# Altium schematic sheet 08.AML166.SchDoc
size A3; CheckedBy: <审核人员>; Author: 刘时杰; DocumentNumber: 7; SheetNumber: 7; SheetTotal: 8; PageSetup: Record=PageOptions|CenterHorizontal=True|CenterVertical=True|PrintScale=1.00|XCorrection=1.00|YCorrection=1.00|PrintKind=0|BorderSize=5000000|LeftOffset=0|BottomOffset=0|Orientation=2|PaperLength=1000|PaperWidth=1000|Scale=100|PaperSource=7|PrintQuality=600|MediaType=1|DitherType=10|PaperKind=A4|PrintScaleMode=1; CheckDate: <审核日期>; SheetName: AML166_ADC24; SheetVersion: Rev.D; SheetDescription: AML166评估24位ADC性能电路; ProductName: AML166; ProductModel: AML166-Core
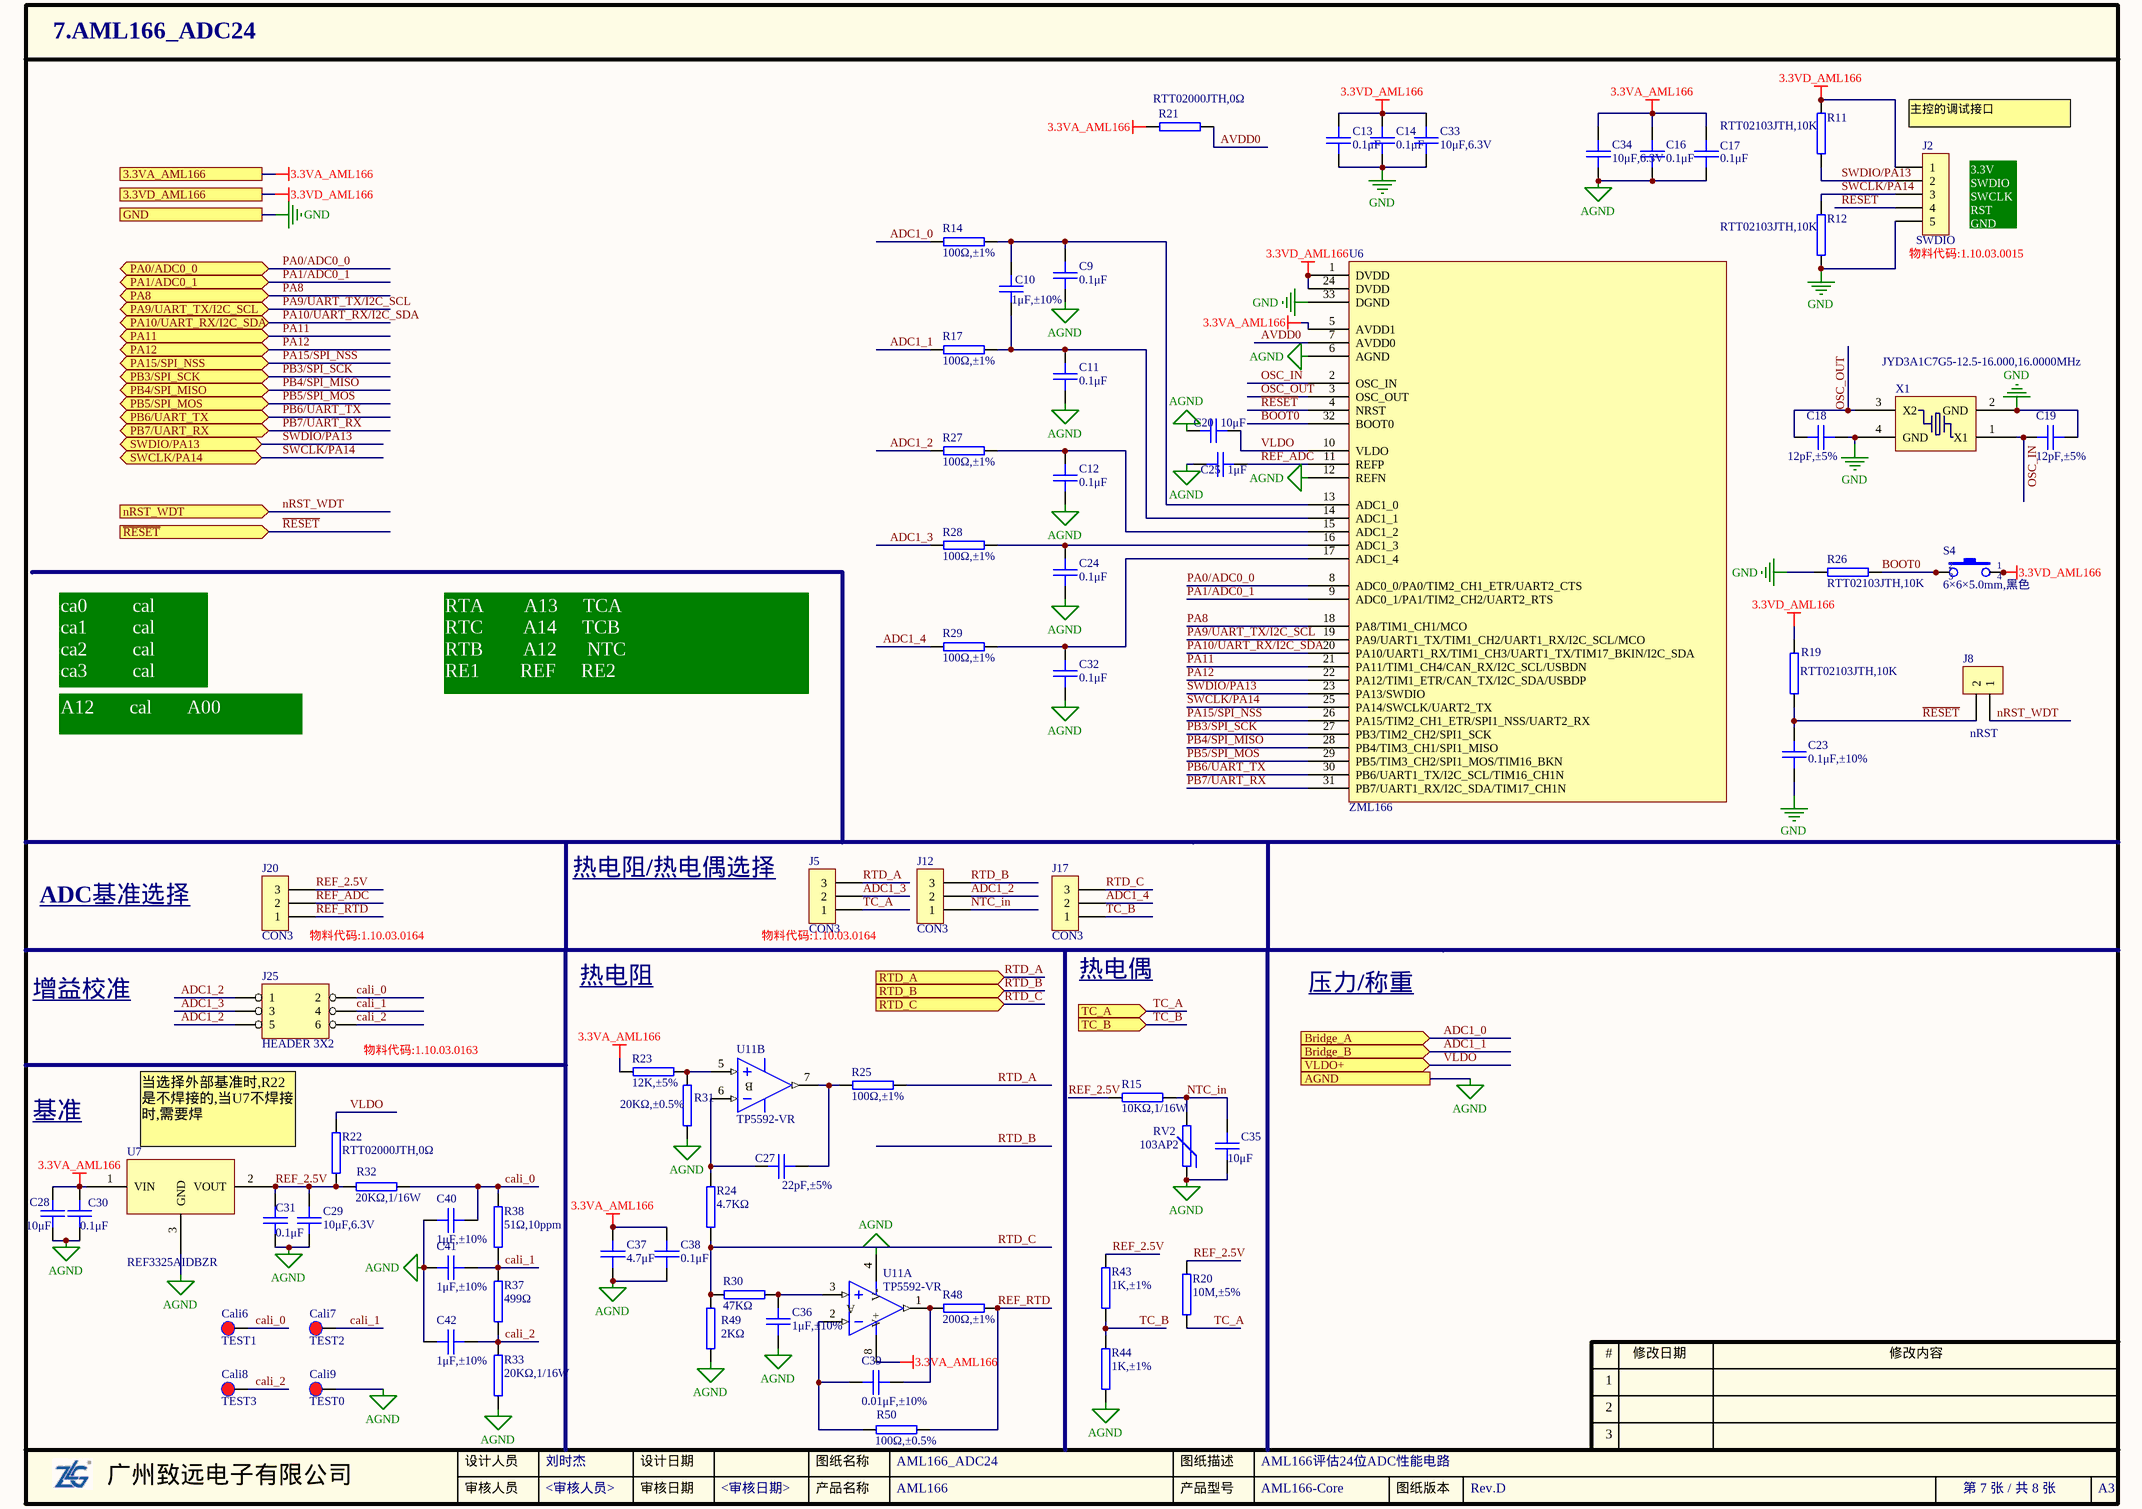
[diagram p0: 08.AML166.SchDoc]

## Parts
C9  0.1μF  [0402C]
C10  1μF,±10%  [0402C]
C11  0.1μF  [0402C]
C12  0.1μF  [0402C]
C13  0.1μF  [0402C]
C14  0.1μF  [0402C]
C16  0.1μF  [0402C]
C17  0.1μF  [0402C]
C18  12pF,±5%  [0402C]
C19  12pF,±5%  [0402C]
C20  10μF  [0603C]
C23  0.1μF,±10%  [0402C]
C24  0.1μF  [0402C]
C25  1μF  [0402C]
C27  22pF,±5%  [0402C]
C28  10μF  [0603C]
C29  10μF,6.3V  [0603C]
C30  0.1μF  [0402C]
C31  0.1μF  [0402C]
C32  0.1μF  [0402C]
C33  10μF,6.3V  [0603C]
C34  10μF,6.3V  [0603C]
C35  10μF  [0603C]
C36  1μF,±10%  [0402C]
C37  4.7μF  [0402C]
C38  0.1μF  [0402C]
C39  0.01μF,±10%  [0402C]
C40  1μF,±10%  [0402C]
C41  1μF,±10%  [0402C]
C42  1μF,±10%  [0402C]
Cali6  TEST1  [PAD-25/40]  (no BOM)
Cali7  TEST2  [PAD-25/40]  (no BOM)
Cali8  TEST3  [PAD-25/40]  (no BOM)
Cali9  TEST0  [PAD-25/40]  (no BOM)
J2  SWDIO  [SIP-5-2.54-6.0-R90]
J5  CON3  [SIP-3-2.54]
J8  nRST  [SIP-2-2.54]
J12  CON3  [SIP-3-2.54]
J17  CON3  [SIP-3-2.54]
J20  CON3  [SIP-3-2.54]
J25  HEADER 3X2  [IDC-6-2.54]
R11  RTT02103JTH,10K  [0402R]
R12  RTT02103JTH,10K  [0402R]
R14  100Ω,±1%  [0402R]
R15  10KΩ,1/16W  [0603R]
R17  100Ω,±1%  [0402R]
R19  RTT02103JTH,10K  [0402R]
R20  10M,±5%  [0402R]
R21  RTT02000JTH,0Ω  [0402R]
R22  RTT02000JTH,0Ω  [0402R]  (no BOM)
R23  12K,±5%  [0402R]
R24  4.7KΩ  [0603R]
R25  100Ω,±1%  [0402R]
R26  RTT02103JTH,10K  [0402R]
R27  100Ω,±1%  [0402R]
R28  100Ω,±1%  [0402R]
R29  100Ω,±1%  [0402R]
R30  47KΩ  [0603R]
R31  20KΩ,±0.5%  [0402R]
R32  20KΩ,1/16W  [0603R]
R33  20KΩ,1/16W  [0603R]
R37  499Ω  [0603R]
R38  51Ω,10ppm  [0603R]
R43  1K,±1%  [0402R]
R44  1K,±1%  [0402R]
R48  200Ω,±1%  [0402R]
R49  2KΩ  [0603R]
R50  100Ω,±0.5%  [0402R]
RV2  103AP2  [RESRR254W35L380T260H850P]
S4  value 6×6×5.0mm,黑色  [KEY-6S]  (hidden comment: SW-PB4P)
U6  ZML166  [QFN50P500X500X85-33N]
U7  REF3325AIDBZR  [SOT-23]
U11  TP5592-VR  [SOP65P490X120-8N]  (parts A,B of 2)
X1  JYD3A1C7G5-12.5-16.000,16.0000MHz  [OSCCC250X320X80-4N]

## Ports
3.3VA_AML166, 3.3VD_AML166, AGND, Bridge_A (in), Bridge_B (in), GND, nRST_WDT (in), PA0/ADC0_0 (bidir), PA1/ADC0_1 (bidir), PA8 (bidir), PA9/UART_TX/I2C_SCL (bidir), PA10/UART_RX/I2C_SDA (bidir), PA11 (bidir), PA12 (bidir), PA15/SPI_NSS (bidir), PB3/SPI_SCK (bidir), PB4/SPI_MISO (bidir), PB5/SPI_MOS (bidir), PB6/UART_TX (bidir), PB7/UART_RX (bidir), RTD_A (in), RTD_B (in), RTD_C (in), SWCLK/PA14 (bidir), SWDIO/PA13 (bidir), TC_A (in), TC_B (in), VLDO+ (in), ~{RESET} (in)

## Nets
3.3VA_AML166: C16.1 C17.1 C28.2 C30.1 C34.2 C37.1 C38.1 R21.1 R23.1 U6.5(AVDD1) U7.1(VIN) U11.8(V+) ; port 3.3VA_AML166
3.3VD_AML166: C13.1 C14.1 C33.2 J2.1 R11.2 R19.1 S4.1 S4.4 U6.1(DVDD) U6.24(DVDD) ; port 3.3VD_AML166
AGND: C9.2 C11.2 C12.2 C16.2 C17.2 C20.2 C24.2 C25.1 C28.1 C29.1 C30.2 C31.2 C32.2 C34.1 C35.1 C36.2 C37.2 C38.2 C40.1 C41.1 C42.1 Cali9.1 R31.1 R33.2 R44.2 R49.1 RV2.1 U6.6(AGND) U6.12(REFN) U7.3(GND) U11.4(V-) ; port AGND
GND: C13.2 C14.2 C18.1 C19.2 C23.2 C33.1 J2.5 R12.1 R26.2 U6.33(DGND) X1.2(GND) X1.4(GND) ; port GND
ADC1_0: R14.1 ; port Bridge_A
ADC1_1: R17.1 ; port Bridge_B
ADC1_2: J12.2 J25.1 J25.5 R27.1
ADC1_3: J5.2 J25.3 R28.1
ADC1_4: J17.2 R29.1
AVDD0: R21.2 U6.7(AVDD0)
BOOT0: R26.1 S4.2 S4.3 U6.32(BOOT0)
cali_0: C40.2 Cali6.1 J25.2 R32.1 R38.1
cali_1: C41.2 Cali7.1 J25.4 R37.2 R38.2
cali_2: C42.2 Cali8.1 J25.6 R33.1 R37.1
nRST_WDT: J8.1 ; port nRST_WDT
NTC_in: C35.2 J12.1 R15.2 RV2.2
OSC_IN: C19.1 U6.2(OSC_IN) X1.1(X1)
OSC_OUT: C18.2 U6.3(OSC_OUT) X1.3(X2)
PA0/ADC0_0: U6.8(ADC0_0/PA0/TIM2_CH1_ETR/UART2_CTS) ; port PA0/ADC0_0
PA1/ADC0_1: U6.9(ADC0_1/PA1/TIM2_CH2/UART2_RTS) ; port PA1/ADC0_1
PA8: U6.18(PA8/TIM1_CH1/MCO) ; port PA8
PA9/UART_TX/I2C_SCL: U6.19(PA9/UART1_TX/TIM1_CH2/UART1_RX/I2C_SCL/MCO) ; port PA9/UART_TX/I2C_SCL
PA10/UART_RX/I2C_SDA: U6.20(PA10/UART1_RX/TIM1_CH3/UART1_TX/TIM17_BKIN/I2C_SDA) ; port PA10/UART_RX/I2C_SDA
PA11: U6.21(PA11/TIM1_CH4/CAN_RX/I2C_SCL/USBDN) ; port PA11
PA12: U6.22(PA12/TIM1_ETR/CAN_TX/I2C_SDA/USBDP) ; port PA12
PA15/SPI_NSS: U6.26(PA15/TIM2_CH1_ETR/SPI1_NSS/UART2_RX) ; port PA15/SPI_NSS
PB3/SPI_SCK: U6.27(PB3/TIM2_CH2/SPI1_SCK) ; port PB3/SPI_SCK
PB4/SPI_MISO: U6.28(PB4/TIM3_CH1/SPI1_MISO) ; port PB4/SPI_MISO
PB5/SPI_MOS: U6.29(PB5/TIM3_CH2/SPI1_MOS/TIM16_BKN) ; port PB5/SPI_MOS
PB6/UART_TX: U6.30(PB6/UART1_TX/I2C_SCL/TIM16_CH1N) ; port PB6/UART_TX
PB7/UART_RX: U6.31(PB7/UART1_RX/I2C_SDA/TIM17_CH1N) ; port PB7/UART_RX
~{RESET}: C23.1 J2.4 J8.2 R19.2 U6.4(NRST) ; port ~{RESET}
REF_2.5V: C29.2 C31.1 J20.3 R15.1 R20.2 R22.1 R32.2 R43.2 U7.2(VOUT)
REF_ADC: C25.2 J20.2 U6.11(REFP)
REF_RTD: J20.1 R48.2 R50.1
RTD_A: J5.3 R25.2 ; port RTD_A
RTD_B: J12.3 ; port RTD_B
RTD_C: J17.3 R24.1 R30.1 R49.2 ; port RTD_C
SWCLK/PA14: J2.3 R12.2 U6.25(PA14/SWCLK/UART2_TX) ; port SWCLK/PA14
SWDIO/PA13: J2.2 R11.1 U6.23(PA13/SWDIO) ; port SWDIO/PA13
TC_A: J5.1 R20.1 ; port TC_A
TC_B: J17.1 R43.1 R44.1 ; port TC_B
VLDO: C20.1 R22.2 U6.10(VLDO) ; port VLDO+
NetC9_1: C9.1 C10.1 R14.2 U6.13(ADC1_0)
NetC10_2: C10.2 C11.1 R17.2 U6.14(ADC1_1)
NetC12_1: C12.1 R27.2 U6.15(ADC1_2)
NetC24_1: C24.1 R28.2 U6.16(ADC1_3)
NetC27_1: C27.1 R24.2 U11.6(IN-)
NetC27_2: C27.2 R25.1 U11.7(OUT)
NetC32_1: C32.1 R29.2 U6.17(ADC1_4)
NetC36_1: C36.1 R30.2 U11.3(IN+)
NetC39_1: C39.1 R50.2 U11.2(IN-)
NetC39_2: C39.2 R48.1 U11.1(OUT)
NetR23_2: R23.2 R31.2 U11.5(IN+)

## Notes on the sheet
- (near J2) 主控的调试接口
- (near J2) 3.3V
  SWDIO
  SWCLK
  RST
  GND
- (near J2) 物料代码:1.10.03.0015
- ca0         cal
  ca1         cal
  ca2         cal
  ca3         cal
- RTA        A13     TCA
  RTC        A14     TCB
  RTB        A12      NTC
  RE1        REF     RE2
- A12       cal       A00
- ADC基准选择
- 热电阻/热电偶选择
- (near J20) 物料代码:1.10.03.0164
- 热电阻
- (near J5) 物料代码:1.10.03.0164
- (near J17) 热电偶
- 压力/称重
- 增益校准
- (near J25) 物料代码:1.10.03.0163
- 基准
- 当选择外部基准时,R22是不焊接的,当U7不焊接时,需要焊

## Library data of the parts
C9 C11-C14 C16 C17 C24 C30-C32 C38 = 1.02.17.0118: GCM155R71E104KE02D,0.1μF,±10%,25V,X7R,0402,muRata,RoHS; 名称: 电容; 封装: 0402; 贴片和直插: SMT; PCB备注: 161012yjh; 器件优选方案: 正常状态，可以选用
C10 C25 C36 C40-C42 = 1.02.17.0092: GRM155R61C105KA12D,1μF,±10% ,16V,X5R,0402,muRata,RoHS; 名称: 电容; 封装: 0402; 贴片和直插: SMT; PCB备注: 无数据手册，依据采购部提供的信息添加的封装。; 器件优选方案: 正常状态，可以选用
C18 C19 = 1.02.17.0018: GRM1555C1H120JA01D,12pF,±5%,50V,C0G,0402,muRata,RoHS; 名称: 电容; 封装: 0402; 设备封装名称: C0402_12PF_COG_50V_5%; 贴片和直插: SMT; 器件优选方案: 正常状态，可以选用
C20 C28 C29 C33-C35 = 1.02.01.0065: 10μF,6.3V,X5R,GRM188R60J106M****,0603,Murata,RoHS; 名称: 电容; 封装: 0603; 贴片和直插: SMT; 器件优选方案: 正常状态，可以选用
C23 = 1.02.17.0006: GRM155R71C104KA88D,0.1μF,±10%,16V,X7R,0402,muRata,RoHS; 名称: 电容; 封装: 0402; 设备封装名称: C0402_0.1uF_X7R_16V_10%; 贴片和直插: SMT; 器件优选方案: 正常状态，可以选用
C27 = 1.02.17.0036: GRM1555C1H220JA01D,22pF,±5%,50V,C0G,0402,muRata,RoHS; 名称: 电容; 封装: 0402; 设备封装名称: C0402_22PF_NPO_50V_5%; 贴片和直插: SMT; 器件优选方案: 正常状态，可以选用
C37 = 1.02.17.0073: GRM155R60J475ME87D,4.7μF,±20%,6.3V,X5R,0402,muRata,RoHS; 名称: 电容; 封装: 0402; 贴片和直插: SMT; 器件优选方案: 正常状态，可以选用
C39 = 1.02.17.0019: GRM155R71H103KA88D,0.01μF,±10%,50V,X7R,0402,muRata,RoHS; 名称: 电容; 封装: 0402; 设备封装名称: C0402_0.01uF_X7R_50V_10%; 贴片和直插: SMT; 器件优选方案: 正常状态，可以选用
Cali6-Cali9 = TEST-DOT
J2 = CON5: Connector; 物料代码: 1.10.03.0015
J5 J12 J17 J20 = CON3: Connector
J8 = CON2: Connector; 物料代码: 1.10.03.0164
R11 R12 R19 R26 = 1.01.17.0006: RTT02103JTH,10K,±5%,0402,RALEC,RoHS; 名称: 电阻; 封装: 0402; 设备封装名称: R0402_10K; 贴片和直插: SMT; 器件优选方案: 正常状态，可以选用
R14 R17 R25 R27-R29 = 1.01.17.0029: 100Ω,±1%,0402,RALEC,RoHS; 名称: 电阻; 封装: 0402; 设备封装名称: R0402_100R_1%; 贴片和直插: SMT; 器件优选方案: 正常状态，可以选用
R15 = 1.01.01.0192: 10KΩ,1/16W,10PPM/℃,±0.1%,0603,Viking,RoHS; 名称: 电阻; 封装: 0603; 设备封装名称: R0603_10K_0.1%; 贴片和直插: SMT; 器件优选方案: 临时/偏门物料/不主推物料，谨慎选用
R20 = 1.01.17.0005: 10M,±5%,0402,RALEC,RoHS; 名称: 电阻; 封装: 0402; 设备封装名称: R0402_10M; 贴片和直插: SMT; 器件优选方案: 正常状态，可以选用
R21 R22 = 1.01.17.0004: RTT02000JTH,0Ω,±5%,0402,RALEC,RoHS; 名称: 电阻; 封装: 0402; 设备封装名称: R0402_0R; 贴片和直插: SMT; 器件优选方案: 正常状态，可以选用
R23 = 1.01.17.0035: 12K,±5%,0402,RALEC,RoHS; 名称: 电阻; 封装: 0402; 设备封装名称: R0402_12K; 贴片和直插: SMT; 器件优选方案: 正常状态，可以选用
R24 = 1.01.01.0045: 4.7KΩ,0603,*,RoHS; 名称: 电阻; 封装: 0603; 设备封装名称: R0603_4.7K; 厂商: Ralec; 贴片和直插: SMT; 器件优选方案: 正常状态，可以选用
R30 = 1.01.01.0060: 47KΩ,0603,*,RoHS; 名称: 电阻; 封装: 0603; 设备封装名称: R0603_47K; 厂商: Ralec; 贴片和直插: SMT; 器件优选方案: 正常状态，可以选用
R31 = 1.01.17.0053: 20KΩ,±0.5%,0402,RoHS; 名称: 电阻; 封装: 0402; 设备封装名称: R0402_20K_0.5%; 厂商: Ralec; 贴片和直插: SMT; 器件优选方案: 正常状态，可以选用
R32 R33 = 1.01.01.0207: 20KΩ,1/16W,10PPM/℃,±0.1%,0603,Viking,RoHS; 名称: 电阻; 封装: 0603; 贴片和直插: SMT; 器件优选方案: 临时/偏门物料/不主推物料，谨慎选用
R37 = 1.01.01.0155: 499Ω,RN731JTTD,4990B10,0603,KOA,RoHS; 名称: 电阻; 封装: 0603; 设备封装名称: R0603_499R_0.1%; 贴片和直插: SMT; 器件优选方案: 临时/偏门物料/不主推物料，谨慎选用
R38 = 1.01.01.0215: 51Ω,10ppm,±0.1%,AR03BTB0510,0603,Viking,RoHS; 名称: 电阻; 封装: 0603; 贴片和直插: SMT; 器件优选方案: 临时/偏门物料/不主推物料，谨慎选用
R43 R44 = 1.01.17.0016: 1K,±1%,0402,RALEC,RoHS; 名称: 电阻; 封装: 0402; 设备封装名称: R0402_1K_1%; 贴片和直插: SMT; 器件优选方案: 正常状态，可以选用
R48 = 1.01.17.0073: 200Ω,±1%,0402,RoHS; 名称: 电阻; 封装: 0402; 设备封装名称: R0402_200R_1%; 厂商: Ralec; 贴片和直插: SMT; 器件优选方案: 正常状态，可以选用
R49 = 1.01.01.0157: 2KΩ,RN731JTTD,2001B10,0603,KOA,RoHS; 名称: 电阻; 封装: 0603; 设备封装名称: R0603_2K_0.1%; 贴片和直插: SMT; 器件优选方案: 临时/偏门物料/不主推物料，谨慎选用
R50 = 1.01.17.0052: 100Ω,±0.5%,0402,RoHS; 名称: 电阻; 封装: 0402; 设备封装名称: R0402_100R_0.5%; 厂商: Ralec; 贴片和直插: SMT; 器件优选方案: 正常状态，可以选用
RV2 = 1.01.14.0020: 103AP2,SIP,semitec,RoHS; 名称: 热敏电阻(临时); 贴片和直插: THT; PCB备注: 171205CZY; 器件优选方案: 临时/偏门物料/不主推物料，谨慎选用
S4 = 1.09.01.0003: 6×6×5.0mm,黑色,SMD,,*; 名称: 轻触按键; 贴片和直插: SMT
U7 = 1.05.10.0334: REF3325AIDBZR,SOT-23,TI; 名称: 集成电路; 设备封装名称: SOT-23_REF3325AIDBZR; 贴片和直插: SMT; 器件优选方案: 量产物料,优先选用
U11 = 1.05.20.0102: TP5592-VR,MSOP-8,3PEAK,RoHS; 名称: 集成电路(临时); 贴片和直插: SMT; PCB备注: 170810lmd; 器件优选方案: 临时/偏门物料/不主推物料，谨慎选用
X1 = 1.07.03.0077: JYD3A1C7G5-12.5-16.000,16.0000MHz,±10ppm,12.5pF,-40~85℃,SMD3225,JYEG,RoHS; 名称: 晶体; 贴片和直插: SMT; PCB备注: 151225lmd171128ZW; 器件优选方案: 正常状态，可以选用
